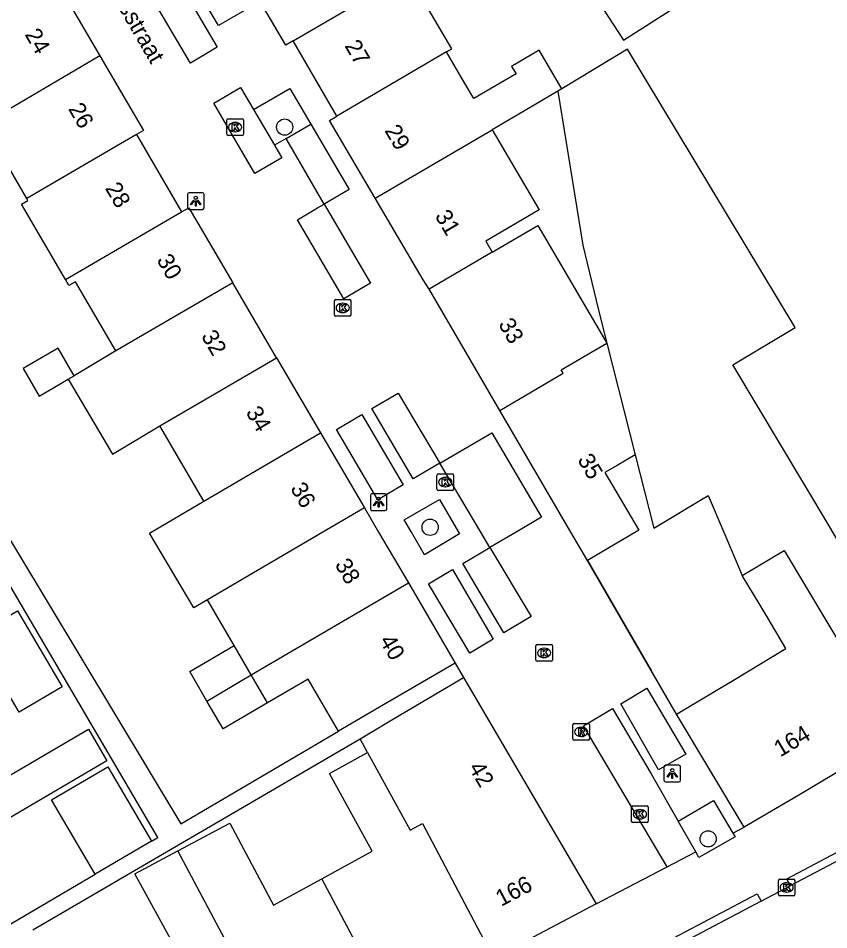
# Model space of a CAD drawing. Extents: x 161771 to 163125, y 382479 to 383177.
# Drawn here: x 162315 to 162363.8, y 382726.1 to 382780.9 of the extents above; entities that cross this region are included whole.
import ezdxf

# ---------------------------------------------------------------- set-up
doc = ezdxf.new("R2010")
doc.units = 0
for name, color, linetype in [('IMGEO_Boom', 7, 'Continuous'), ('IMGEO_Kolk', 7, 'Continuous'), ('IMGEO_Lichtpunt', 7, 'Continuous'), ('IMGEO_Muur', 7, 'Continuous'), ('IMGEO_Openbare_ruimte_label', 7, 'Continuous'), ('IMGEO_Pand', 7, 'Continuous'), ('IMGEO_Pand_nummerreeks', 7, 'Continuous'), ('IMGEO_Parkeervlak_open', 7, 'Continuous'), ('IMGEO_Rijbaan_lokaal_open', 7, 'Continuous'), ('IMGEO_Rioolput', 7, 'Continuous'), ('IMGEO_Voetpad_open', 7, 'Continuous'), ('IMGEO_Woonerf_open', 7, 'Continuous')]:
    doc.layers.add(name, color=color, linetype=linetype)

msp = doc.modelspace()

# ---------------------------------------------------------------- linework, layer by layer
at = {"layer": 'IMGEO_Boom'}
for centre in [(162331.039, 382774.384), (162339.799, 382750.293), (162356.546, 382731.533)]:
    msp.add_circle(centre, 0.489, dxfattribs=at)
at = {"layer": 'IMGEO_Kolk'}
for p, q in [((162327.55, 382773.962), (162327.55, 382774.814)), ((162327.625, 382774.888), (162328.477, 382774.888)), ((162328.551, 382774.814), (162328.551, 382773.962)), ((162328.038, 382774.668), (162328.063, 382774.668)), ((162328.477, 382773.888), (162327.625, 382773.888)), ((162328.061, 382774.108), (162328.036, 382774.108)), ((162334.031, 382763.075), (162334.031, 382763.927)), ((162334.106, 382764.001), (162334.958, 382764.001)), ((162334.519, 382763.781), (162334.544, 382763.781)), ((162335.032, 382763.927), (162335.032, 382763.075)), ((162334.542, 382763.221), (162334.517, 382763.221)), ((162334.958, 382763.001), (162334.106, 382763.001)), ((162340.212, 382752.587), (162340.212, 382753.439)), ((162340.287, 382753.513), (162341.139, 382753.513)), ((162340.7, 382753.293), (162340.725, 382753.293)), ((162341.213, 382753.439), (162341.213, 382752.587)), ((162341.139, 382752.513), (162340.287, 382752.513)), ((162340.723, 382752.733), (162340.698, 382752.733)), ((162346.164, 382742.301), (162346.164, 382743.153)), ((162346.239, 382743.227), (162347.091, 382743.227)), ((162346.652, 382743.007), (162346.677, 382743.007)), ((162347.165, 382743.153), (162347.165, 382742.301)), ((162346.675, 382742.447), (162346.65, 382742.447)), ((162347.091, 382742.227), (162346.239, 382742.227)), ((162351.935, 382732.591), (162351.935, 382733.443)), ((162352.01, 382733.517), (162352.862, 382733.517)), ((162352.423, 382733.297), (162352.448, 382733.297)), ((162352.936, 382733.443), (162352.936, 382732.591)), ((162352.862, 382732.517), (162352.01, 382732.517)), ((162352.446, 382732.737), (162352.421, 382732.737)), ((162360.774, 382728.18), (162360.774, 382729.032)), ((162360.849, 382729.106), (162361.701, 382729.106)), ((162361.262, 382728.886), (162361.287, 382728.886)), ((162361.775, 382729.032), (162361.775, 382728.18)), ((162361.701, 382728.106), (162360.849, 382728.106)), ((162361.285, 382728.326), (162361.26, 382728.326))]:
    msp.add_line(p, q, dxfattribs=at)
for points in [[(162327.55, 382773.962), (162327.55, 382774.814)], [(162327.625, 382774.888), (162328.477, 382774.888)], [(162328.551, 382774.814), (162328.551, 382773.962)], [(162327.871, 382774.588), (162327.994, 382774.588), (162327.994, 382774.437), (162328.124, 382774.588), (162328.288, 382774.588), (162328.142, 382774.437), (162328.295, 382774.188), (162328.143, 382774.188), (162328.058, 382774.352), (162327.994, 382774.285), (162327.994, 382774.188), (162327.871, 382774.188), (162327.871, 382774.588)], [(162328.477, 382773.888), (162327.625, 382773.888)], [(162334.031, 382763.075), (162334.031, 382763.927)], [(162334.106, 382764.001), (162334.958, 382764.001)], [(162335.032, 382763.927), (162335.032, 382763.075)], [(162334.352, 382763.701), (162334.475, 382763.701), (162334.475, 382763.55), (162334.605, 382763.701), (162334.769, 382763.701), (162334.623, 382763.55), (162334.776, 382763.301), (162334.624, 382763.301), (162334.539, 382763.465), (162334.475, 382763.398), (162334.475, 382763.301), (162334.352, 382763.301), (162334.352, 382763.701)], [(162334.958, 382763.001), (162334.106, 382763.001)], [(162340.212, 382752.587), (162340.212, 382753.439)], [(162340.287, 382753.513), (162341.139, 382753.513)], [(162341.213, 382753.439), (162341.213, 382752.587)], [(162340.533, 382753.213), (162340.656, 382753.213), (162340.656, 382753.062), (162340.786, 382753.213), (162340.95, 382753.213), (162340.804, 382753.062), (162340.957, 382752.813), (162340.805, 382752.813), (162340.72, 382752.977), (162340.656, 382752.91), (162340.656, 382752.813), (162340.533, 382752.813), (162340.533, 382753.213)], [(162341.139, 382752.513), (162340.287, 382752.513)], [(162346.164, 382742.301), (162346.164, 382743.153)], [(162346.239, 382743.227), (162347.091, 382743.227)], [(162346.485, 382742.927), (162346.608, 382742.927), (162346.608, 382742.776), (162346.738, 382742.927), (162346.902, 382742.927), (162346.756, 382742.776), (162346.909, 382742.527), (162346.757, 382742.527), (162346.672, 382742.691), (162346.608, 382742.624), (162346.608, 382742.527), (162346.485, 382742.527), (162346.485, 382742.927)], [(162347.165, 382743.153), (162347.165, 382742.301)], [(162347.091, 382742.227), (162346.239, 382742.227)], [(162351.935, 382732.591), (162351.935, 382733.443)], [(162352.01, 382733.517), (162352.862, 382733.517)], [(162352.256, 382733.217), (162352.379, 382733.217), (162352.379, 382733.066), (162352.509, 382733.217), (162352.673, 382733.217), (162352.527, 382733.066), (162352.68, 382732.817), (162352.528, 382732.817), (162352.443, 382732.981), (162352.379, 382732.914), (162352.379, 382732.817), (162352.256, 382732.817), (162352.256, 382733.217)], [(162352.936, 382733.443), (162352.936, 382732.591)], [(162352.862, 382732.517), (162352.01, 382732.517)], [(162360.774, 382728.18), (162360.774, 382729.032)], [(162360.849, 382729.106), (162361.701, 382729.106)], [(162361.095, 382728.806), (162361.218, 382728.806), (162361.218, 382728.655), (162361.348, 382728.806), (162361.512, 382728.806), (162361.366, 382728.655), (162361.519, 382728.406), (162361.367, 382728.406), (162361.282, 382728.57), (162361.218, 382728.503), (162361.218, 382728.406), (162361.095, 382728.406), (162361.095, 382728.806)], [(162361.775, 382729.032), (162361.775, 382728.18)], [(162361.701, 382728.106), (162360.849, 382728.106)]]:
    msp.add_lwpolyline(points, dxfattribs=at)
for centre, start, end in [((162327.627, 382774.812), 91.552, 178.448), ((162327.627, 382774.812), 91.552, 178.448), ((162328.475, 382774.812), 1.552, 88.448), ((162328.475, 382774.812), 1.552, 88.448), ((162327.627, 382773.964), 181.552, 268.448), ((162327.627, 382773.964), 181.552, 268.448), ((162328.475, 382773.964), 271.552, 358.448), ((162328.475, 382773.964), 271.552, 358.448), ((162334.108, 382763.925), 91.552, 178.448), ((162334.108, 382763.925), 91.552, 178.448), ((162334.956, 382763.925), 1.552, 88.448), ((162334.956, 382763.925), 1.552, 88.448), ((162334.108, 382763.077), 181.552, 268.448), ((162334.108, 382763.077), 181.552, 268.448), ((162334.956, 382763.077), 271.552, 358.448), ((162334.956, 382763.077), 271.552, 358.448), ((162340.289, 382753.437), 91.552, 178.448), ((162340.289, 382753.437), 91.552, 178.448), ((162341.137, 382753.437), 1.552, 88.448), ((162341.137, 382753.437), 1.552, 88.448), ((162340.289, 382752.589), 181.552, 268.448), ((162340.289, 382752.589), 181.552, 268.448), ((162341.137, 382752.589), 271.552, 358.448), ((162341.137, 382752.589), 271.552, 358.448), ((162346.241, 382743.151), 91.552, 178.448), ((162346.241, 382743.151), 91.552, 178.448), ((162347.089, 382743.151), 1.552, 88.448), ((162347.089, 382743.151), 1.552, 88.448), ((162346.241, 382742.303), 181.552, 268.448), ((162346.241, 382742.303), 181.552, 268.448), ((162347.089, 382742.303), 271.552, 358.448), ((162347.089, 382742.303), 271.552, 358.448), ((162352.012, 382733.441), 91.552, 178.448), ((162352.012, 382733.441), 91.552, 178.448), ((162352.86, 382733.441), 1.552, 88.448), ((162352.86, 382733.441), 1.552, 88.448), ((162352.012, 382732.593), 181.552, 268.448), ((162352.012, 382732.593), 181.552, 268.448), ((162352.86, 382732.593), 271.552, 358.448), ((162352.86, 382732.593), 271.552, 358.448), ((162360.851, 382729.03), 91.552, 178.448), ((162360.851, 382729.03), 91.552, 178.448), ((162361.699, 382729.03), 1.552, 88.448), ((162361.699, 382729.03), 1.552, 88.448), ((162360.851, 382728.182), 181.552, 268.448), ((162360.851, 382728.182), 181.552, 268.448), ((162361.699, 382728.182), 271.552, 358.448), ((162361.699, 382728.182), 271.552, 358.448)]:
    msp.add_arc(centre, 0.0765, start, end, dxfattribs=at)
for centre, major_axis, ratio, start_param, end_param in [((162328.037, 382774.388), (-0.387, 0.002), 0.722429, 4.712389, 7.853982), ((162328.062, 382774.388), (-0.39, 0.002), 0.717154, 1.570796, 4.712389), ((162334.518, 382763.501), (-0.387, 0.002), 0.722429, 4.712389, 7.853982), ((162334.543, 382763.501), (-0.39, 0.002), 0.717154, 1.570796, 4.712389), ((162340.699, 382753.013), (-0.387, 0.002), 0.722429, 4.712389, 7.853982), ((162340.724, 382753.013), (-0.39, 0.002), 0.717154, 1.570796, 4.712389), ((162346.651, 382742.727), (-0.387, 0.002), 0.722429, 4.712389, 7.853982), ((162346.676, 382742.727), (-0.39, 0.002), 0.717154, 1.570796, 4.712389), ((162352.422, 382733.017), (-0.387, 0.002), 0.722429, 4.712389, 7.853982), ((162352.447, 382733.017), (-0.39, 0.002), 0.717154, 1.570796, 4.712389), ((162361.261, 382728.606), (-0.387, 0.002), 0.722429, 4.712389, 7.853982), ((162361.286, 382728.606), (-0.39, 0.002), 0.717154, 1.570796, 4.712389)]:
    msp.add_ellipse(centre, major_axis=major_axis, ratio=ratio, start_param=start_param, end_param=end_param, dxfattribs=at)
at = {"layer": 'IMGEO_Lichtpunt'}
for p, q in [((162325.182, 382770.332), (162325.182, 382769.525)), ((162325.182, 382770.332), (162325.182, 382769.525)), ((162326.084, 382770.427), (162325.276, 382770.427)), ((162326.084, 382770.427), (162325.276, 382770.427)), ((162326.178, 382769.525), (162326.178, 382770.332)), ((162326.178, 382769.525), (162326.178, 382770.332)), ((162325.276, 382769.431), (162326.084, 382769.431)), ((162325.276, 382769.431), (162326.084, 382769.431)), ((162336.198, 382752.21), (162336.198, 382751.403)), ((162336.198, 382752.21), (162336.198, 382751.403)), ((162337.1, 382752.305), (162336.292, 382752.305)), ((162337.1, 382752.305), (162336.292, 382752.305)), ((162337.194, 382751.403), (162337.194, 382752.21)), ((162337.194, 382751.403), (162337.194, 382752.21)), ((162336.292, 382751.309), (162337.1, 382751.309)), ((162336.292, 382751.309), (162337.1, 382751.309)), ((162353.884, 382735.867), (162353.884, 382735.06)), ((162353.884, 382735.867), (162353.884, 382735.06)), ((162354.786, 382735.962), (162353.978, 382735.962)), ((162354.786, 382735.962), (162353.978, 382735.962)), ((162354.88, 382735.06), (162354.88, 382735.867)), ((162354.88, 382735.06), (162354.88, 382735.867)), ((162353.978, 382734.966), (162354.786, 382734.966)), ((162353.978, 382734.966), (162354.786, 382734.966))]:
    msp.add_line(p, q, dxfattribs=at)
for points in [[(162325.556, 382769.996), (162325.595, 382769.968), (162325.407, 382769.706), (162325.369, 382769.733), (162325.556, 382769.996)], [(162325.658, 382769.948), (162325.705, 382769.948), (162325.705, 382769.626), (162325.658, 382769.626), (162325.658, 382769.948)], [(162325.768, 382769.968), (162325.806, 382769.995), (162325.993, 382769.733), (162325.954, 382769.705), (162325.768, 382769.968)], [(162336.572, 382751.874), (162336.611, 382751.846), (162336.423, 382751.584), (162336.385, 382751.611), (162336.572, 382751.874)], [(162336.674, 382751.826), (162336.721, 382751.826), (162336.721, 382751.504), (162336.674, 382751.504), (162336.674, 382751.826)], [(162336.784, 382751.846), (162336.822, 382751.873), (162337.009, 382751.611), (162336.97, 382751.583), (162336.784, 382751.846)], [(162354.258, 382735.531), (162354.297, 382735.503), (162354.109, 382735.241), (162354.071, 382735.268), (162354.258, 382735.531)], [(162354.36, 382735.483), (162354.407, 382735.483), (162354.407, 382735.161), (162354.36, 382735.161), (162354.36, 382735.483)], [(162354.47, 382735.503), (162354.508, 382735.53), (162354.695, 382735.268), (162354.656, 382735.24), (162354.47, 382735.503)]]:
    msp.add_lwpolyline(points, dxfattribs=at)
for centre in [(162325.681, 382770.13), (162336.697, 382752.008), (162354.383, 382735.665)]:
    msp.add_circle(centre, 0.0994, dxfattribs=at)
for centre, start, end in [((162325.276, 382770.332), 90, 180), ((162325.276, 382770.332), 90, 180), ((162326.084, 382770.332), 0, 90), ((162326.084, 382770.332), 0, 90), ((162325.276, 382769.525), 180, 270), ((162325.276, 382769.525), 180, 270), ((162326.084, 382769.525), 270, 0), ((162326.084, 382769.525), 270, 360), ((162336.292, 382752.21), 90, 180), ((162336.292, 382752.21), 90, 180), ((162337.1, 382752.21), 0, 90), ((162337.1, 382752.21), 0, 90), ((162336.292, 382751.403), 180, 270), ((162336.292, 382751.403), 180, 270), ((162337.1, 382751.403), 270, 0), ((162337.1, 382751.403), 270, 360), ((162353.978, 382735.867), 90, 180), ((162353.978, 382735.867), 90, 180), ((162354.786, 382735.867), 0, 90), ((162354.786, 382735.867), 0, 90), ((162353.978, 382735.06), 180, 270), ((162353.978, 382735.06), 180, 270), ((162354.786, 382735.06), 270, 0), ((162354.786, 382735.06), 270, 360)]:
    msp.add_arc(centre, 0.0946, start, end, dxfattribs=at)
at = {"layer": 'IMGEO_Muur'}
msp.add_lwpolyline([(162349.271, 382748.299), (162353.117, 382741.669)], dxfattribs=at)
at = {"layer": 'IMGEO_Pand'}
for points in [[(162351.442, 382779.613), (162358.934, 382784.413), (162356.966, 382787.629), (162349.685, 382782.357), (162351.442, 382779.613)], [(162331.544, 382779.569), (162331.112, 382779.316), (162328.465, 382783.836)], [(162331.544, 382779.569), (162338.209, 382783.479)], [(162340.784, 382778.917), (162341.104, 382779.105), (162338.576, 382783.419), (162338.329, 382783.274), (162338.209, 382783.479)], [(162317.289, 382783.149), (162319.911, 382778.67)], [(162334.172, 382775.038), (162331.544, 382779.569)], [(162319.911, 382778.67), (162312.888, 382774.571)], [(162319.911, 382778.67), (162322.534, 382774.189), (162322.103, 382773.937)], [(162340.784, 382778.917), (162334.172, 382775.038)], [(162347.725, 382776.699), (162346.368, 382779.013), (162344.709, 382778.041), (162344.973, 382777.589), (162342.435, 382776.102), (162341.817, 382777.155), (162340.784, 382778.917)], [(162373.426, 382740.995), (162370.859, 382745.286), (162369.334, 382747.836), (162366.401, 382746.082), (162365.318, 382747.892), (162364.056, 382750), (162363.767, 382750.483), (162358.025, 382760.073), (162361.791, 382762.328), (162351.697, 382779.077), (162347.725, 382776.699)], [(162347.486, 382776.556), (162346.074, 382775.711), (162343.533, 382774.228)], [(162347.725, 382776.699), (162347.486, 382776.556)], [(162347.486, 382776.556), (162349.006, 382767.28), (162349.938, 382763.369), (162350.441, 382761.385)], [(162336.496, 382770.099), (162333.742, 382774.786), (162334.172, 382775.038)], [(162315.505, 382770.086), (162312.888, 382774.571)], [(162336.496, 382770.099), (162343.533, 382774.228)], [(162343.533, 382774.228), (162346.364, 382769.397), (162343.148, 382767.512), (162343.535, 382766.852)], [(162322.103, 382773.937), (162315.505, 382770.086)], [(162322.103, 382773.937), (162324.828, 382769.281)], [(162317.837, 382765.2), (162315.182, 382769.75), (162315.569, 382769.976), (162315.505, 382770.086)], [(162339.733, 382764.622), (162339.379, 382765.193), (162336.496, 382770.099)], [(162317.837, 382765.2), (162324.828, 382769.281)], [(162324.828, 382769.281), (162325.259, 382769.533), (162327.905, 382765.014)], [(162343.535, 382766.852), (162346.291, 382768.467), (162350.441, 382761.385)], [(162343.535, 382766.852), (162339.733, 382764.622)], [(162320.875, 382760.909), (162318.433, 382765.079), (162318.041, 382764.851), (162317.837, 382765.2)], [(162327.905, 382765.014), (162320.875, 382760.909)], [(162330.551, 382760.494), (162327.905, 382765.014)], [(162343.997, 382757.332), (162339.858, 382764.42), (162339.733, 382764.622)], [(162318.362, 382759.417), (162317.397, 382761.07), (162315.293, 382759.842), (162316.257, 382758.189), (162318.001, 382759.203)], [(162343.997, 382757.332), (162347.805, 382759.565), (162347.685, 382759.77), (162350.441, 382761.385)], [(162350.441, 382761.385), (162352.146, 382754.659)], [(162320.875, 382760.909), (162318.362, 382759.417)], [(162323.52, 382756.39), (162330.551, 382760.494)], [(162330.551, 382760.494), (162333.196, 382755.976)], [(162318.001, 382759.203), (162318.362, 382759.417)], [(162318.001, 382759.203), (162320.674, 382754.703), (162323.52, 382756.39)], [(162349.271, 382748.299), (162348.278, 382750), (162343.997, 382757.332)], [(162326.165, 382751.873), (162323.52, 382756.39)], [(162326.165, 382751.873), (162333.196, 382755.976)], [(162333.196, 382755.976), (162335.842, 382751.457)], [(162352.146, 382754.659), (162351.055, 382754.02), (162350.321, 382753.59), (162352.361, 382750.11), (162352.173, 382750), (162349.271, 382748.299)], [(162352.146, 382754.659), (162353.265, 382750.246), (162356.548, 382752.212), (162357.49, 382750), (162358.601, 382747.391)], [(162326.391, 382745.924), (162325.568, 382745.437), (162322.903, 382749.946), (162326.165, 382751.873)], [(162335.842, 382751.457), (162333.345, 382750), (162326.391, 382745.924)], [(162335.842, 382751.457), (162336.695, 382750), (162338.487, 382746.939)], [(162358.601, 382747.391), (162361.116, 382748.897), (162367.842, 382737.655)], [(162354.64, 382739.044), (162358.167, 382741.154), (162361.233, 382742.988), (162360.155, 382744.791), (162359.67, 382745.603), (162358.601, 382747.391)], [(162329.021, 382741.4), (162331.479, 382742.849), (162338.487, 382746.939)], [(162338.487, 382746.939), (162341.308, 382742.121)], [(162327.992, 382743.17), (162326.391, 382745.924)], [(162314.936, 382745.271), (162317.633, 382740.689), (162315.038, 382739.162), (162312.341, 382743.743), (162314.936, 382745.271)], [(162326.357, 382739.829), (162325.318, 382741.616), (162327.992, 382743.17)], [(162329.021, 382741.4), (162327.992, 382743.17)], [(162341.308, 382742.121), (162336.992, 382739.597), (162334.281, 382738.012)], [(162326.357, 382739.829), (162329.021, 382741.4)], [(162330.001, 382739.714), (162329.021, 382741.4)], [(162335.582, 382737.558), (162337.492, 382738.692), (162341.806, 382741.253)], [(162341.806, 382741.253), (162349.794, 382727.612)], [(162334.281, 382738.012), (162332.451, 382741.138), (162330.001, 382739.714)], [(162330.001, 382739.714), (162327.327, 382738.16), (162326.357, 382739.829)], [(162358.717, 382732.229), (162354.64, 382739.044)], [(162308.493, 382735.355), (162310.024, 382732.754), (162319.223, 382738.132), (162320.333, 382736.234), (162311.14, 382730.859)], [(162336.034, 382736.735), (162335.582, 382737.558)], [(162367.842, 382737.655), (162362.258, 382734.314), (162358.717, 382732.229)], [(162333.269, 382729.131), (162336.3, 382730.793), (162333.734, 382735.474), (162336.034, 382736.735)], [(162336.034, 382736.735), (162338.6, 382732.053), (162339.331, 382732.454), (162343.623, 382724.345)], [(162319.628, 382729.406), (162316.994, 382733.878), (162320.379, 382735.872), (162323.014, 382731.397)], [(162324.592, 382730.811), (162327.726, 382732.479), (162330.358, 382727.536), (162333.269, 382729.131)], [(162323.014, 382731.397), (162319.628, 382729.406)], [(162321.429, 382722.643), (162324.739, 382724.457), (162322.01, 382729.437), (162324.592, 382730.811)], [(162331.462, 382717.908), (162327.244, 382725.83), (162324.592, 382730.811)], [(162337.534, 382721.122), (162333.269, 382729.131)], [(162349.794, 382727.612), (162343.623, 382724.345)]]:
    msp.add_lwpolyline(points, dxfattribs=at)
at = {"layer": 'IMGEO_Parkeervlak_open'}
for points in [[(162325.358, 382778.234), (162322.307, 382783.407), (162323.94, 382784.359), (162326.979, 382779.19), (162325.358, 382778.234)], [(162330.419, 382773.291), (162330.864, 382772.531), (162329.249, 382771.585), (162326.765, 382775.826), (162328.38, 382776.772), (162329.158, 382775.444)], [(162329.158, 382775.444), (162330.419, 382773.291)], [(162331.128, 382773.702), (162332.612, 382774.563)], [(162332.612, 382774.563), (162334.915, 382770.632), (162333.417, 382769.755)], [(162333.417, 382769.755), (162331.128, 382773.702)], [(162333.417, 382769.755), (162336.203, 382764.999), (162334.591, 382764.054), (162331.804, 382768.81), (162333.018, 382769.521), (162333.417, 382769.755)], [(162340.387, 382754.148), (162338.778, 382753.2), (162336.283, 382757.435), (162337.875, 382758.372), (162340.387, 382754.148)], [(162338.176, 382752.845), (162336.657, 382751.951), (162334.163, 382756.186), (162335.681, 382757.08), (162338.176, 382752.845)], [(162343.404, 382749.075), (162345.878, 382744.913), (162344.232, 382743.935), (162341.772, 382748.114), (162343.404, 382749.075)], [(162341.141, 382747.742), (162343.603, 382743.561), (162342.189, 382742.72), (162339.705, 382746.897), (162341.141, 382747.742)], [(162351.278, 382739.665), (162352.856, 382740.602), (162355.21, 382736.64), (162353.546, 382735.69), (162351.278, 382739.665)], [(162354.077, 382729.857), (162349.039, 382738.335), (162350.786, 382739.372), (162353.119, 382735.446), (162354.746, 382732.595)], [(162355.795, 382730.757), (162354.746, 382732.595)]]:
    msp.add_lwpolyline(points, dxfattribs=at)
at = {"layer": 'IMGEO_Rijbaan_lokaal_open'}
for points in [[(162364.87, 382730.497), (162361.487, 382728.709)], [(162359.733, 382727.782), (162361.487, 382728.709)], [(162359.733, 382727.782), (162352.24, 382723.821), (162349.484, 382722.364)]]:
    msp.add_lwpolyline(points, dxfattribs=at)
at = {"layer": 'IMGEO_Rioolput'}
for p, q in [((162348.471, 382738.476), (162349.323, 382738.476)), ((162348.396, 382737.55), (162348.396, 382738.402)), ((162348.884, 382738.256), (162348.909, 382738.256)), ((162349.397, 382738.402), (162349.397, 382737.55)), ((162349.323, 382737.476), (162348.471, 382737.476)), ((162348.907, 382737.696), (162348.882, 382737.696))]:
    msp.add_line(p, q, dxfattribs=at)
for points in [[(162348.471, 382738.476), (162349.323, 382738.476)], [(162348.396, 382737.55), (162348.396, 382738.402)], [(162348.985, 382738.174), (162348.733, 382738.176), (162348.733, 382737.776)], [(162348.733, 382737.776), (162348.857, 382737.776), (162348.857, 382737.938), (162348.868, 382737.938)], [(162348.911, 382738.095), (162348.857, 382738.095), (162348.857, 382738.014)], [(162348.857, 382738.014), (162348.909, 382738.014)], [(162349.397, 382738.402), (162349.397, 382737.55)], [(162349.323, 382737.476), (162348.471, 382737.476)], [(162348.915, 382737.909), (162348.986, 382737.776), (162349.126, 382737.776), (162349.061, 382737.902)]]:
    msp.add_lwpolyline(points, dxfattribs=at)
for centre, radius, start, end in [((162348.473, 382738.4), 0.0765, 91.552, 178.448), ((162348.473, 382738.4), 0.0765, 91.552, 178.448), ((162349.321, 382738.4), 0.0765, 1.552, 88.448), ((162349.321, 382738.4), 0.0765, 1.552, 88.448), ((162348.867, 382737.885), 0.0533, 26.0293, 88.6989), ((162348.893, 382738.203), 0.19, 274.7715, 282.9687), ((162348.917, 382737.999), 0.0964, 77.0061, 93.1865), ((162348.931, 382738.056), 0.0378, 276.6634, 79.6772), ((162348.984, 382738.064), 0.109, 350.3612, 89.416), ((162348.982, 382738.064), 0.112, 277.5842, 350.9817), ((162348.966, 382737.849), 0.108, 29.5134, 73.7905), ((162348.473, 382737.552), 0.0765, 181.552, 268.448), ((162348.473, 382737.552), 0.0765, 181.552, 268.448), ((162349.321, 382737.552), 0.0765, 271.552, 358.448), ((162349.321, 382737.552), 0.0765, 271.552, 358.448)]:
    msp.add_arc(centre, radius, start, end, dxfattribs=at)
for centre, major_axis, ratio, start_param, end_param in [((162348.883, 382737.976), (-0.387, 0.002), 0.722429, 4.712389, 7.853982), ((162348.908, 382737.976), (-0.39, 0.002), 0.717154, 1.570796, 4.712389)]:
    msp.add_ellipse(centre, major_axis=major_axis, ratio=ratio, start_param=start_param, end_param=end_param, dxfattribs=at)
at = {"layer": 'IMGEO_Voetpad_open'}
for points in [[(162323.014, 382731.397), (162323.401, 382731.624), (162306.253, 382760.786), (162289.568, 382788.823), (162284.629, 382797.122)], [(162302.938, 382768.724), (162324.79, 382732.441), (162334.281, 382738.012)], [(162341.308, 382742.121), (162341.806, 382741.253)], [(162315.862, 382726.049), (162335.582, 382737.558)], [(162358.035, 382731.885), (162358.717, 382732.229)], [(162358.035, 382731.885), (162358.174, 382731.65), (162355.992, 382730.412), (162355.795, 382730.757)], [(162361.487, 382728.709), (162361.291, 382729.126), (162364.658, 382730.912), (162364.87, 382730.497)], [(162354.077, 382729.857), (162355.795, 382730.757)], [(162349.794, 382727.612), (162354.077, 382729.857)], [(162313.959, 382726.072), (162319.628, 382729.406)], [(162348.919, 382722.065), (162348.686, 382722.507), (162351.968, 382724.242), (162359.5, 382728.224), (162359.733, 382727.782)]]:
    msp.add_lwpolyline(points, dxfattribs=at)
at = {"layer": 'IMGEO_Woonerf_open'}
for points in [[(162327.056, 382780.499), (162324.565, 382784.723), (162326.143, 382785.643), (162328.62, 382781.405), (162327.056, 382780.499)], [(162329.158, 382775.444), (162331.352, 382776.714), (162332.612, 382774.563)], [(162331.128, 382773.702), (162330.419, 382773.291)], [(162340.387, 382754.148), (162343.509, 382755.987), (162346.506, 382750.902), (162344.975, 382750), (162343.404, 382749.075)], [(162343.404, 382749.075), (162342.854, 382750), (162340.387, 382754.148)], [(162340.365, 382751.964), (162341.508, 382750), (162341.564, 382749.904), (162339.452, 382748.643), (162338.67, 382750), (162338.243, 382750.74), (162340.365, 382751.964)], [(162354.64, 382739.044), (162353.117, 382741.669), (162349.271, 382748.299)], [(162354.746, 382732.595), (162356.871, 382733.844), (162358.035, 382731.885)]]:
    msp.add_lwpolyline(points, dxfattribs=at)

# ---------------------------------------------------------------- texts
at = {"layer": 'IMGEO_Openbare_ruimte_label'}
msp.add_text('Franciscus Sonniusstraat', height=1, rotation=299.9511, dxfattribs=at).set_placement((162315.497, 382791.141))
at = {"layer": 'IMGEO_Pand_nummerreeks'}
for s, rotation, p in [('24', 300.344, (162315.352, 382779.966)), ('27', 300.1202, (162334.623, 382779.283)), ('26', 300.3436, (162317.975, 382775.486)), ('29', 300.5442, (162337.03, 382774.174)), ('28', 300.3379, (162320.194, 382770.705)), ('31', 300.5438, (162340.059, 382769.039)), ('30', 300.3494, (162323.299, 382766.386)), ('33', 300.2806, (162343.881, 382762.528)), ('32', 300.3494, (162325.98, 382761.807)), ('34', 300.3481, (162328.667, 382757.221)), ('35', 300.2806, (162348.647, 382754.365)), ('36', 300.3481, (162331.351, 382752.637)), ('38', 300.3494, (162334.035, 382748.05)), ('40', 300.3481, (162336.719, 382743.466)), ('164', 30.8913, (162360.888, 382736.431)), ('42', 300.3551, (162342.087, 382735.825)), ('166', 27.8973, (162344.08, 382727.438))]:
    msp.add_text(s, height=1, rotation=rotation, dxfattribs=at).set_placement(p)

doc.saveas('drawing.dxf')
